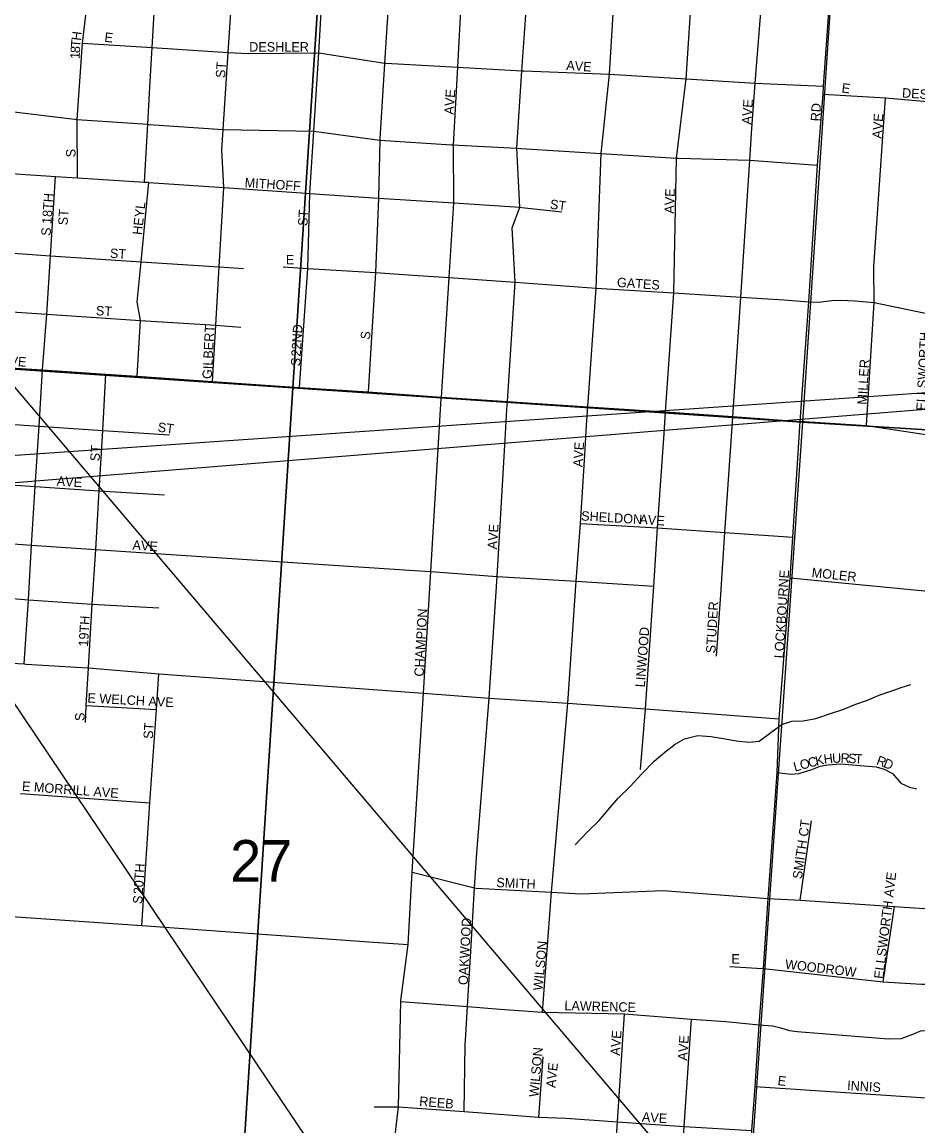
# Model space of a CAD drawing. Extents: x 0 to 34, y -6.2 to 22.
# Drawn here: x 7.798 to 8.697, y 15.431 to 16.538 of the extents above; entities that cross this region are included whole.
import ezdxf

# ---------------------------------------------------------------- set-up
doc = ezdxf.new("R2010")
doc.units = 0
for name, color, linetype in [('GM_X_City_Street', 7, 'Continuous'), ('GM_X_City_Street_Text', 7, 'Continuous'), ('GM_X_Corporation', 7, 'Continuous'), ('GM_X_Minor_River', 7, 'Continuous'), ('GM_X_Section', 7, 'Continuous'), ('GM_X_Section_Text', 7, 'Continuous'), ('SH_Data', 7, 'Continuous')]:
    doc.layers.add(name, color=color, linetype=linetype)

msp = doc.modelspace()

# ---------------------------------------------------------------- linework, layer by layer
at = {"layer": 'GM_X_City_Street'}
for points in [[(8.4421, 16.1254), (8.4436, 16.147), (8.4518, 16.2663), (8.4547, 16.4014), (8.4642, 16.4807), (8.4694, 16.5573), (8.4733, 16.6188), (8.4777, 16.6819), (8.4816, 16.7408), (8.4858, 16.7964), (8.49, 16.8567), (8.4943, 16.9177), (8.4995, 16.9928), (8.5047, 17.0684), (8.5092, 17.1285), (8.5109, 17.1608), (8.5058, 17.1659), (8.5097, 17.2843), (8.5097, 17.2851), (8.5205, 17.4178), (8.5236, 17.4524), (8.5259, 17.4883)], [(8.231, 16.4146), (8.2352, 16.4924), (8.2393, 16.5689), (8.2394, 16.5702), (8.2429, 16.629), (8.2467, 16.6916), (8.2561, 16.7563), (8.2598, 16.8119), (8.2636, 16.8724), (8.2673, 16.9332), (8.2719, 17.0085), (8.2769, 17.0837), (8.2805, 17.1442), (8.2833, 17.1808), (8.2886, 17.3017), (8.2975, 17.4278)], [(8.2224, 17.4243), (8.2147, 17.3096), (8.2143, 17.3045), (8.2133, 17.2551), (8.2092, 17.1856), (8.2072, 17.1498), (8.2031, 17.0891), (8.198, 17.0133), (8.1934, 16.9379), (8.1898, 16.8774), (8.1861, 16.8166), (8.1847, 16.793), (8.1826, 16.7608), (8.1791, 16.7028), (8.175, 16.6396), (8.1667, 16.574), (8.1619, 16.4965), (8.1618, 16.496), (8.1573, 16.4207)], [(8.2846, 16.1494), (8.2851, 16.1573), (8.293, 16.2771), (8.2899, 16.3313), (8.2975, 16.3521), (8.2946, 16.4113), (8.2965, 16.4428), (8.2997, 16.4888), (8.3048, 16.5639), (8.3089, 16.6244), (8.3095, 16.6328), (8.3129, 16.6869), (8.3231, 16.7514), (8.327, 16.8072), (8.3312, 16.8678), (8.3348, 16.9288), (8.3398, 17.004), (8.3448, 17.0791), (8.3487, 17.1399), (8.3514, 17.1759), (8.3563, 17.2545), (8.3509, 17.2945), (8.3548, 17.3409), (8.3603, 17.425)], [(8.3645, 16.1336), (8.3656, 16.152), (8.3741, 16.2711), (8.379, 16.4061), (8.3874, 16.4856), (8.392, 16.5628), (8.3905, 16.6184), (8.3943, 16.6812), (8.4034, 16.7463), (8.4072, 16.8018), (8.4113, 16.8621), (8.4155, 16.9232), (8.4202, 16.9983), (8.425, 17.0739), (8.429, 17.1341), (8.4316, 17.1706), (8.4327, 17.1898)], [(7.8541, 16.3816), (7.8538, 16.4399), (7.859, 16.5166), (7.8688, 16.5981), (7.8724, 16.6597), (7.877, 16.7322)], [(8.5785, 16.1374), (8.5873, 16.2574), (8.5961, 16.3941), (8.6018, 16.4654), (8.6021, 16.4733), (8.6072, 16.5475), (8.6159, 16.6733), (8.6204, 16.7316), (8.6205, 16.7332)], [(7.9895, 16.1775), (7.9926, 16.2338), (7.996, 16.2923), (8.0008, 16.3717), (7.9987, 16.4096), (8.0001, 16.43), (8.0051, 16.5073), (8.0091, 16.5672), (8.01, 16.5844), (8.0182, 16.6502), (8.0234, 16.722)], [(8.0874, 16.3714), (8.0911, 16.4282), (8.0959, 16.5067), (8.1005, 16.5827), (8.1045, 16.6443), (8.1084, 16.7076), (8.109, 16.7163), (8.1093, 16.7212)], [(8.5106, 16.1365), (8.511, 16.1424), (8.5192, 16.262), (8.528, 16.3993), (8.5303, 16.4311), (8.5334, 16.4765), (8.5394, 16.5517), (8.5475, 16.678), (8.5506, 16.7265)], [(7.9137, 16.1826), (7.9171, 16.2386), (7.9137, 16.2572), (7.9177, 16.2973), (7.9256, 16.3768), (7.9211, 16.3771), (7.9244, 16.4352), (7.9266, 16.4725), (7.9288, 16.5122), (7.9331, 16.5878)], [(7.859, 16.5166), (7.9288, 16.5122), (8.0051, 16.5073), (8.0251, 16.5061), (8.0959, 16.5067), (8.1619, 16.4965), (8.1623, 16.4964), (8.163, 16.4964)], [(8.163, 16.4964), (8.1633, 16.4964), (8.2352, 16.4924), (8.2997, 16.4888), (8.3014, 16.4887), (8.3874, 16.4856), (8.4642, 16.4807), (8.5334, 16.4765), (8.6021, 16.4733)], [(8.6018, 16.4654), (8.6643, 16.4617), (8.7291, 16.4561), (8.7852, 16.452), (8.8361, 16.4437), (8.9104, 16.438), (8.9114, 16.438), (9.0018, 16.4311), (9.0207, 16.4296), (9.0755, 16.4258)], [(7.5818, 16.4625), (7.6093, 16.4607), (7.6413, 16.4586), (7.7056, 16.4543), (7.7709, 16.4499), (7.8538, 16.4399), (7.9244, 16.4352), (7.926, 16.435), (8.0001, 16.43), (8.0911, 16.4282), (8.1572, 16.4193), (8.229, 16.4147), (8.231, 16.4146), (8.2365, 16.4143)], [(8.6452, 16.1332), (8.6527, 16.2566), (8.6524, 16.2924), (8.6643, 16.4617)], [(8.1573, 16.4207), (8.1572, 16.4193), (8.1557, 16.3612), (8.1529, 16.2866), (8.1453, 16.1671)], [(8.2188, 16.1604), (8.2189, 16.1618), (8.2267, 16.2816), (8.2312, 16.3565), (8.231, 16.4146)], [(8.2365, 16.4143), (8.2946, 16.4113), (8.2987, 16.4111), (8.379, 16.4061), (8.4547, 16.4014), (8.4566, 16.4013), (8.528, 16.3993), (8.5961, 16.3941)], [(7.5716, 16.4001), (7.605, 16.398), (7.6375, 16.396), (7.7017, 16.3915), (7.767, 16.3873), (7.8273, 16.3831)], [(7.8006, 15.8943), (7.8049, 15.9586), (7.808, 16.0134), (7.8116, 16.0721), (7.8155, 16.1327), (7.8189, 16.189), (7.8234, 16.2448), (7.827, 16.3034), (7.832, 16.3828)], [(7.8273, 16.3831), (7.832, 16.3828), (7.8541, 16.3816), (7.9211, 16.3771), (7.9256, 16.3768), (8.0008, 16.3717), (8.0785, 16.3666)], [(8.0767, 16.1715), (8.0848, 16.2907), (8.087, 16.366), (8.0874, 16.3714)], [(8.0785, 16.3666), (8.087, 16.366), (8.1557, 16.3612), (8.2312, 16.3565), (8.2975, 16.3521), (8.2997, 16.3518)], [(8.2997, 16.3518), (8.3397, 16.3474)], [(7.567, 16.3248), (7.6004, 16.3184), (7.6321, 16.3162), (7.6964, 16.312), (7.7619, 16.308), (7.827, 16.3034), (7.9177, 16.2973), (7.996, 16.2923), (8.0205, 16.2908)], [(8.0602, 16.2924), (8.0848, 16.2907), (8.1529, 16.2866), (8.1905, 16.2841), (8.2267, 16.2816), (8.293, 16.2771), (8.3741, 16.2711), (8.4518, 16.2663), (8.5192, 16.262), (8.5625, 16.2591)], [(7.5624, 16.2625), (7.5967, 16.26), (7.6288, 16.258), (7.6924, 16.2538), (7.758, 16.2491), (7.8234, 16.2448), (7.9171, 16.2386), (7.9926, 16.2338), (8.0178, 16.2319)], [(8.5625, 16.2591), (8.5873, 16.2574), (8.5974, 16.2569), (8.6101, 16.2587), (8.6194, 16.2589), (8.6334, 16.2581), (8.6527, 16.2566), (8.7107, 16.2447), (8.7233, 16.244), (8.7468, 16.2415), (8.7772, 16.245), (8.8224, 16.2459), (8.8269, 16.2457), (8.9179, 16.2418), (9.0755, 16.2339)], [(7.5593, 16.2056), (7.5926, 16.2036), (7.6247, 16.2016), (7.6889, 16.1974), (7.7542, 16.1931), (7.8189, 16.189), (7.8824, 16.1846), (7.9137, 16.1826), (7.9895, 16.1775), (8.0767, 16.1715), (8.1453, 16.1671)], [(7.8649, 15.8904), (7.8688, 15.9543), (7.8723, 16.0091), (7.8759, 16.0678), (7.8795, 16.1284), (7.8824, 16.1846)], [(8.1453, 16.1671), (8.2189, 16.1618), (8.2851, 16.1573), (8.3656, 16.152), (8.4436, 16.147), (8.511, 16.1424), (8.5785, 16.1374), (8.5829, 16.1372)], [(8.163, 15.3396), (8.176, 15.4504), (8.1782, 15.5559), (8.1782, 15.557), (8.1854, 15.613), (8.1897, 15.6855), (8.2011, 15.8649), (8.2084, 15.987), (8.2188, 16.1604)], [(7.5442, 16.1507), (7.5551, 16.1501), (7.5894, 16.1478), (7.6222, 16.1455), (7.6859, 16.1413), (7.7507, 16.1369), (7.8155, 16.1327), (7.8795, 16.1284), (7.9464, 16.124)], [(8.2829, 16.1194), (8.2846, 16.1494)], [(8.3626, 16.1037), (8.3645, 16.1336)], [(8.499, 15.964), (8.5032, 16.0261), (8.5106, 16.1365)], [(8.524, 15.3221), (8.5303, 15.4266), (8.5334, 15.4708), (8.5376, 15.5324), (8.5419, 15.5889), (8.5466, 15.6592), (8.5554, 15.7853), (8.5577, 15.8394), (8.5686, 15.9805), (8.5712, 16.0212), (8.5785, 16.1374)], [(8.5829, 16.1372), (8.6452, 16.1332), (8.7045, 16.1243), (8.9007, 16.112), (9.0755, 16.1)], [(8.4218, 15.829), (8.4234, 15.8494), (8.4318, 15.9722), (8.4357, 16.0307), (8.4421, 16.1254)], [(8.2667, 15.86), (8.2667, 15.86), (8.2748, 15.9818), (8.2829, 16.1194)], [(8.3202, 15.5453), (8.3292, 15.6655), (8.3456, 15.855), (8.3541, 15.9772), (8.3582, 16.0351), (8.3626, 16.1037)], [(7.5507, 16.0897), (7.5515, 16.0897), (7.5852, 16.0873), (7.6184, 16.0849), (7.6819, 16.0807), (7.7471, 16.0765), (7.8116, 16.0721), (7.8759, 16.0678), (7.9414, 16.0637)], [(6.9041, 16.0718), (6.9394, 16.0696), (6.9657, 16.0678), (7.0046, 16.0653), (7.0745, 16.0608), (7.1366, 16.0569), (7.2035, 16.0528), (7.2737, 16.0484), (7.3389, 16.044), (7.4485, 16.0372), (7.5121, 16.0334), (7.5478, 16.0311), (7.5817, 16.0286), (7.6147, 16.0262), (7.6782, 16.0219), (7.7433, 16.0179), (7.808, 16.0134), (7.8723, 16.0091), (7.9326, 16.0051)], [(8.3582, 16.0351), (8.4357, 16.0307), (8.5032, 16.0261), (8.5712, 16.0212)], [(7.9326, 16.0051), (8.2022, 15.9874)], [(8.2022, 15.9874), (8.2084, 15.987), (8.2748, 15.9818), (8.3541, 15.9772), (8.4318, 15.9722)], [(8.5686, 15.9805), (8.7932, 15.959), (8.8895, 15.9534), (9.068, 15.9419), (9.0755, 15.9415)], [(7.5445, 15.9777), (7.5783, 15.9751), (7.6111, 15.9727), (7.675, 15.9681), (7.7396, 15.9638), (7.8049, 15.9586), (7.8688, 15.9543), (7.9355, 15.9504)], [(8.4948, 15.9019), (8.499, 15.964)], [(7.6797, 15.898), (7.7349, 15.8946), (7.7473, 15.8937), (7.7762, 15.896), (7.7884, 15.8952), (7.8006, 15.8943), (7.8026, 15.8942)], [(7.8026, 15.8942), (7.8641, 15.8904)], [(7.8621, 15.8356), (7.8627, 15.8525), (7.8649, 15.8904)], [(7.8641, 15.8904), (7.8649, 15.8904), (7.9357, 15.8843), (8.2011, 15.8649), (8.2667, 15.86), (8.3456, 15.855), (8.4234, 15.8494), (8.5577, 15.8394)], [(7.9333, 15.8485), (7.9357, 15.8843)], [(8.2434, 15.5221), (8.2434, 15.5226), (8.2451, 15.5508), (8.2483, 15.6064), (8.2522, 15.6697), (8.2543, 15.705), (8.2667, 15.86)], [(7.8627, 15.8525), (7.9333, 15.8485)], [(7.9186, 15.6322), (7.9266, 15.7549), (7.9333, 15.8485)], [(8.4186, 15.7883), (8.4218, 15.829)], [(8.5554, 15.7853), (8.5692, 15.7837), (8.5775, 15.7845), (8.5902, 15.7886), (8.5987, 15.7917), (8.6062, 15.7933), (8.619, 15.794), (8.6548, 15.7912), (8.663, 15.7888), (8.6713, 15.7844), (8.6794, 15.7749), (8.6882, 15.7707), (8.6957, 15.7691)], [(7.7969, 15.7645), (7.8568, 15.7602), (7.9266, 15.7549)], [(8.5786, 15.6575), (8.59, 15.737)], [(8.1897, 15.6855), (8.2522, 15.6697), (8.2536, 15.6696), (8.3292, 15.6655), (8.359, 15.6638), (8.4413, 15.6672), (8.5466, 15.6592), (8.5786, 15.6575), (8.6731, 15.651), (8.7437, 15.6465), (8.7826, 15.6433), (8.8034, 15.6424), (8.8705, 15.6384), (8.8872, 15.637), (8.9776, 15.621), (9.053, 15.6257)], [(8.6618, 15.5756), (8.6731, 15.651)], [(7.7883, 15.641), (7.9186, 15.6322), (8.1509, 15.6155), (8.1854, 15.613)], [(8.508, 15.5911), (8.5351, 15.5893)], [(8.5351, 15.5893), (8.5419, 15.5889), (8.6618, 15.5756), (8.6891, 15.5739), (8.7003, 15.5732), (8.7037, 15.5732)], [(8.1782, 15.5559), (8.2451, 15.5508), (8.2778, 15.5483), (8.3202, 15.5453), (8.4024, 15.5434), (8.4695, 15.5383), (8.5041, 15.5358), (8.5309, 15.5331)], [(8.3883, 15.329), (8.3954, 15.4354), (8.4024, 15.5434)], [(8.4546, 15.3243), (8.4624, 15.4307), (8.4695, 15.5383)], [(8.5309, 15.5331), (8.5376, 15.5324), (8.551, 15.5316), (8.5593, 15.5296), (8.5679, 15.527), (8.5756, 15.5257), (8.6008, 15.5239), (8.6667, 15.5185), (8.6801, 15.5189), (8.6934, 15.5238), (8.7003, 15.5267), (8.7123, 15.5257), (8.7745, 15.5212)], [(8.2417, 15.4455), (8.2428, 15.5123), (8.2434, 15.5221)], [(8.3166, 15.4399), (8.321, 15.5006)], [(8.5334, 15.4708), (8.7704, 15.4551), (8.9823, 15.4388), (9.0402, 15.4338)], [(8.1514, 15.4504), (8.176, 15.4504), (8.2417, 15.4455), (8.3166, 15.4399), (8.3436, 15.4388), (8.3954, 15.4354), (8.4624, 15.4307), (8.5303, 15.4266)]]:
    msp.add_lwpolyline(points, dxfattribs=at)
at = {"layer": 'GM_X_Corporation'}
msp.add_lwpolyline([(4.6798, 15.8257), (10.0896, 16.2612), (4.9694, 15.909), (5.0673, 15.9034), (5.0717, 15.8657), (5.0807, 15.8658), (5.0801, 15.8189), (5.099, 15.8198), (5.1009, 15.782), (5.1198, 15.7829), (5.1227, 15.7262), (4.7116, 15.7053)], dxfattribs=at)
at = {"layer": 'GM_X_Minor_River'}
msp.add_lwpolyline([(8.3531, 15.713), (8.365, 15.7255), (8.3772, 15.7375), (8.3879, 15.7499), (8.396, 15.7598), (8.4082, 15.7714), (8.42, 15.7842), (8.4323, 15.7967), (8.443, 15.8057), (8.4533, 15.8139), (8.4628, 15.8192), (8.4761, 15.8225), (8.4889, 15.8216), (8.5018, 15.8196), (8.5146, 15.8172), (8.5275, 15.816), (8.5374, 15.8167), (8.5507, 15.8264), (8.5602, 15.8336), (8.5701, 15.8369), (8.5815, 15.8372), (8.5944, 15.8397), (8.6099, 15.8449), (8.6225, 15.849), (8.6335, 15.8535), (8.646, 15.8579), (8.6578, 15.8631), (8.6704, 15.8672), (8.6799, 15.8706), (8.6897, 15.8735)], dxfattribs=at)
at = {"layer": 'GM_X_Section'}
for points in [[(8.1365, 17.1938), (8.0698, 16.171), (7.5576, 16.2055), (7.6228, 17.2303)], [(8.649, 17.1575), (8.5808, 16.1366), (8.0698, 16.171), (8.1365, 17.1938)], [(7.5576, 16.2055), (8.0698, 16.171), (8.0045, 15.1527), (7.497, 15.1834)], [(8.0698, 16.171), (8.5808, 16.1366), (8.5108, 15.1221), (8.0045, 15.1527)]]:
    msp.add_lwpolyline(points, close=True, dxfattribs=at)
for points in [[(9.0755, 17.1279), (8.649, 17.1575), (8.5808, 16.1366), (9.0755, 16.1062)], [(9.0755, 16.1062), (8.5808, 16.1366), (8.5108, 15.1221), (9.0132, 15.0904), (9.0755, 15.9856)]]:
    msp.add_lwpolyline(points, dxfattribs=at)
at = {"layer": 'SH_Data'}
msp.add_lwpolyline([(9.8345, 13.7654), (6.7618, 17.3841), (9.8345, 12.8156)], close=True, dxfattribs=at)

# ---------------------------------------------------------------- texts
at = {"layer": 'GM_X_City_Street_Text'}
for s, rotation, p in [('T', 85.2137, (7.8567, 16.5121)), ('H', 82.8777, (7.8573, 16.5187)), ('E', 352.8783, (7.8806, 16.5181)), ('8', 86.9068, (7.8564, 16.5064)), ('DESHLER', 0, (8.0262, 16.5081)), ('1', 86.9068, (7.8561, 16.5005)), ('AVE', 356.0569, (8.3439, 16.4897)), ('ST', 86.4254, (8.002, 16.4814)), ('E', 352.8783, (8.6198, 16.4672)), ('AVE', 86.0569, (8.2311, 16.4447)), ('DESHLER', 356.081, (8.6805, 16.4622)), ('AVE', 86.0569, (8.5295, 16.4347)), ('RD', 86.9884, (8.5986, 16.438)), ('AVE', 86.0494, (8.6603, 16.4206)), ('S', 90, (7.852, 16.4021)), ('MITHOFF', 356.2466, (8.0214, 16.3722)), ('S 18TH', 86.0966, (7.827, 16.3231)), ('AVE', 88.0261, (8.452, 16.3455)), ('HEYL', 83.8271, (7.9186, 16.324)), ('ST', 352.4111, (8.3273, 16.3506)), ('ST', 86.4118, (7.844, 16.3337)), ('ST', 86.4262, (8.0845, 16.3331)), ('ST', 356.4262, (7.8863, 16.3014)), ('E', 0, (8.0629, 16.2947)), ('GATES', 356.1833, (8.3947, 16.2722)), ('ST', 356.4254, (7.8722, 16.2439)), ('GILBERT', 87.087, (7.9886, 16.1797)), ('22ND', 86.6354, (8.0778, 16.2022)), ('S', 82.8783, (8.147, 16.219)), ('ELLSWORTH', 87.2752, (8.7045, 16.148)), ('AVE', 356.0574, (7.7772, 16.1939)), ('S', 82.8514, (8.077, 16.1923)), ('MILLER', 86.6998, (8.6453, 16.1539)), ('ST', 352.3968, (7.934, 16.1272)), ('ST', 86.4254, (7.8761, 16.0972)), ('AVE', 86.1806, (8.3603, 16.0914)), ('AVE', 356.0569, (7.833, 16.0731)), ('SHELDON', 356.4804, (8.3588, 16.0381)), ('AVE', 86.0574, (8.2745, 16.0089)), ('AVE', 356.0494, (8.4172, 16.0347)), ('AVE', 356.0569, (7.9089, 16.0089)), ('MOLER', 354.0564, (8.5898, 15.9814)), ('LOCKBOURNE', 86.3857, (8.562, 15.8997)), ('STUDER', 86.8179, (8.4936, 15.9047)), ('CHAMPION', 86.9047, (8.2011, 15.8814)), ('19TH', 86.4254, (7.8645, 15.9114)), ('LINWOOD', 85.6666, (8.4228, 15.8706)), ('E WELCH AVE', 356.922, (7.8638, 15.8556)), ('S', 90, (7.8611, 15.8371)), ('ST', 86.4254, (7.9295, 15.8189)), ('C', 14.8659, (8.5878, 15.7902)), ('K', 13.4583, (8.595, 15.7921)), ('H', 7.2307, (8.6028, 15.794)), ('U', 2.7336, (8.6109, 15.795)), ('R', 357.6191, (8.619, 15.7954)), ('S', 356.7202, (8.6264, 15.7951)), ('T', 356.6384, (8.6331, 15.7947)), ('R', 339.6372, (8.6543, 15.7938)), ('L', 14.8645, (8.5733, 15.7863)), ('O', 14.8735, (8.5797, 15.7881)), ('D', 338.0038, (8.6613, 15.7912)), ('E MORRILL AVE', 355.6848, (7.7981, 15.7672)), ('SMITH CT', 81.9933, (8.5803, 15.6782)), ('20TH', 86.4186, (7.9195, 15.6631)), ('SMITH', 357.3333, (8.2738, 15.6706)), ('ELLSWORTH AVE', 83.0591, (8.662, 15.5782)), ('S', 82.8783, (7.9186, 15.6532)), ('OAKWOOD', 86.9102, (8.2453, 15.5722)), ('WILSON', 84.6138, (8.3203, 15.5665)), ('E', 0, (8.5096, 15.5939)), ('WOODROW', 353.2444, (8.5631, 15.5889)), ('LAWRENCE', 358.5102, (8.3421, 15.5472)), ('AVE', 86.0569, (8.3978, 15.5014)), ('AVE', 86.0569, (8.4653, 15.4964)), ('WILSON', 84.7085, (8.3161, 15.4598)), ('AVE', 84.0977, (8.3332, 15.469)), ('E', 352.8783, (8.5556, 15.4722)), ('INNIS', 356.3452, (8.6255, 15.4672)), ('REEB', 355.0974, (8.1964, 15.4514)), ('AVE', 356.0574, (8.4197, 15.4356))]:
    msp.add_text(s, height=0.00947, rotation=rotation, dxfattribs=at).set_placement(p)
at = {"layer": 'GM_X_Section_Text'}
msp.add_text('27', height=0.04186, rotation=0, dxfattribs=at).set_placement((8.0071, 15.6759))

doc.saveas('drawing.dxf')
